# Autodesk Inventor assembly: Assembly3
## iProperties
Shininess: 64.0
Length Units: 11269
Angle Units: 11279
Time Units: 11290
Mass Units: 11283
Length Display Precision: 3
Angle Display Precision: 2
Created: 2002-01
Part Number: Assembly3
Document SubType Name: Assembly
Designer: ***
Density: 0.0
Volumn: 0.0
Area: 0.0
PropertySet Name: Model Information
Control State: 0
Master: False
Checked Out: False
Author: ***
